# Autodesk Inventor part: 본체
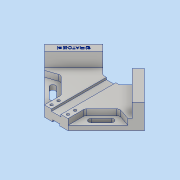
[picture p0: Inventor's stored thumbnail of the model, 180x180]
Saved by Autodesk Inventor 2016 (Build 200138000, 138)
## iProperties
Created: 2019-04
Part Number: 본체
Material: 알루미늄 6061
Document SubType Name: Modeling
Designer: 3sil_cad018
Density: 2.7 g/cm^3
Appearance: 알루미늄 - 평지
Mass: 601.509 g
Surface Area: 426.536 cm^2
Volume: 222.781 cm^3
Author: 3sil_cad018
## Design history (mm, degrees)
sketch "스케치1"
  geometry: L1 (0, -84.853)-(-84.853, 0); L2 (-84.853, 0)-(0, 84.853); L3 (0, 84.853)-(84.853, 0); L4 (84.853, 0)-(0, -84.853); L5 (84.853, 0)-(-84.853, 0); 2 further points
  constraints: 10 end point, 1 coincident, 1 horizontal, 9 other
  dimensions: "d1" = 120 distance of L1.start L1.end
extrude "돌출1" new body sketch "스케치1" distance "d2" = 18; taper "d3" = 0 deg
sketch "스케치2"
  geometry: L1 (0, 18)-(-84.853, 18) reference; L2 (-8, 18)-(-8, 14.5); L3 (-8, 14.5)-(8, 14.5); L4 (8, 14.5)-(8, 18); L5 (84.853, 18)-(0, 18) reference; L6 (0, 0)-(84.853, 0) reference; L7 (8, 0)-(8, 3); L8 (8, 3)-(-8, 3); L9 (-8, 3)-(-8, 0); L10 (8, 0)-(-8, 0); L11 (-84.853, 0)-(0, 0) reference; 1 further point
  constraints: 14 end point, 7 point on line, 4 perpendicular, 1 collinear, 1 midpoint, 1 vertical, 1 vertical alignment
  dimensions: "d4" = 16 distance between parallel lines of L4 L2; "d5" = 3 distance of L7.start L7.end; "d6" = 3.5 distance of L3.end L4.end
extrude "돌출2" cut sketch "스케치2" stored distance "d7" = 1000; taper "d8" = 0 deg
sketch "스케치3"
  geometry: L1 (-84.853, 0)-(-8, -76.853) reference; L2 (-74.246, -10.607)-(10.607, 74.246); L3 (84.853, 0)-(8, 76.853) reference; L4 (8, -76.853)-(84.853, 0) reference; L5 (74.246, -10.607)-(-10.607, 74.246); L6 (-8, 76.853)-(-84.853, 0) reference; L7 (-74.246, -10.607)-(-84.853, 0); L8 (-10.607, 74.246)-(0, 63.64); L9 (10.607, 74.246)-(84.853, 0); L10 (74.246, -10.607)-(84.853, 0); 1 further point
  constraints: 12 end point, 7 point on line, 2 collinear, 1 perpendicular
  dimensions: "d9" = 15 distance between parallel lines of L3 L5; "d10" = 15 distance between parallel lines of L6 L2
extrude "돌출3" join sketch "스케치3" distance "d11" = 24; taper "d12" = 0 deg
sketch "스케치4"
  geometry: L1 (-84.853, 0)-(-8, 76.853) reference; L2 (-35.355, 49.497)-(-14.005, 28.147); L3 (14.005, 28.147)-(35.355, 49.497); L4 (8, 76.853)-(84.853, 0) reference; L5 (-35.355, 49.497)-(0, 84.853); L6 (0, 84.853)-(35.355, 49.497); L7 (-14.005, 28.147)-(14.005, 28.147); L8 (-20, -64.853)-(20, -64.853); L9 (-8, -76.853)-(0, -84.853) reference; L10 (-20, -64.853)-(0, -84.853); L11 (8, -76.853)-(0, -84.853) reference; L12 (0, -84.853)-(20, -64.853); L13 (84.853, 0)-(8, -76.853) reference; 1 further point
  constraints: 16 end point, 2 collinear, 2 horizontal, 2 perpendicular, 2 point on line
  dimensions: "d13" = 50 distance between parallel lines of L2 L6; "d14" = 50 distance between parallel lines of L3 L5; "d15" = 20 distance from line of L9.end L8; "d16" = 93 distance between parallel lines of L8 L7
extrude "돌출4" cut sketch "스케치4" distance "d17" = 100; taper "d18" = 0 deg
node "작업 평면1"
sketch "스케치7"
  geometry: L1 (-35.355, 49.497)-(-84.853, 0) reference; L2 (-49.497, -7.071)-(-20, -36.569); L3 (-74.246, -10.607)-(-20, -64.853) reference; L4 (-20, -64.853)-(-84.853, 0) reference; L5 (-49.497, -7.071)-(-70.711, -14.142); L6 (-70.711, -14.142)-(-42.426, -42.426); L7 (-20, -64.853)-(-8, -64.853) reference; L8 (-20, -64.853)-(-70.711, -14.142); L9 (-20, -64.853)-(-20, -36.569); 1 further point
  constraints: 10 end point, 2 point on line, 1 collinear, 1 perpendicular, 1 vertical
  dimensions: "d31" = 40 distance of L5.end L6.end; "d35" = 63.4349 deg angle of L3 L5; "d38" = 20 distance between parallel lines of L2 L3; "d84" = 20 distance from line of L1 L5.end
extrude "돌출5" cut sketch "스케치7" distance "d39" = 10; taper "d40" = 0 deg
sketch "스케치9"
  geometry: L1 (-20, -64.853)-(-70.711, -14.142) reference; L2 (-35.355, 49.497)-(-84.853, 0) reference; L3 (-49.497, -21.213)-(-32.527, -38.184); L4 (-46.315, -18.031)-(-29.345, -35.002); L5 (-35.709, -41.366)-(-52.679, -24.395); A1 r 4.5 centre (-49.497, -21.213) between (-46.315, -18.031) and (-52.679, -24.395); A2 r 4.5 centre (-32.527, -38.184) between (-35.709, -41.366) and (-29.345, -35.002); 1 further point
  constraints: 6 end point, 4 point on circle, 3 tangent, 2 centre point, 2 coincident
  dimensions: "d46" = 40 distance from line of L2 L3.start; "d48" = 24 distance of L3.start L3.end; "d49" = 9 diameter of A1; "d50" = 9 diameter of A2; "d51" = 10 distance between parallel lines of L1 L3; "d52" = 24 distance of L4.start L4.end
extrude "돌출6" cut sketch "스케치9" distance "d53" = 18; taper "d54" = 0 deg
sketch "스케치10"
  geometry: 1 further point
sketch "스케치11"
  geometry: L1 (-8, -64.853)-(-20, -64.853) reference; L2 (-8, -64.853)-(8, -64.853) reference; 5 further points
  constraints: 4 other
hole "구멍1" sketch "스케치11" at (-14, -46.853), (-14, -58.853), (14, -58.853), (14, -46.853) diameter "d58" = 4.5; stored, may be unused: countersink angle "d62" = 90 deg, drill point angle "d64" = 118 deg; dims "d59" = 6, "d60" = 4, "d61" = 2, "d63" = 8
sketch "스케치12"
  geometry: C1 r 2.25 at (-14, 58.853) reference; C2 r 2.25 at (-14, 46.853) reference; C3 r 2.25 at (14, 46.853) reference; C4 r 2.25 at (14, 58.853) reference; 5 further points
  constraints: 4 coincident
hole "구멍2" sketch "스케치12" at (-14, 58.853), (-14, 46.853), (14, 46.853), (14, 58.853) diameter "d65" = 8; stored, may be unused: countersink angle "d69" = 90 deg, drill point angle "d71" = 0 deg; dims "d66" = 6, "d67" = 4, "d68" = 2, "d70" = 10
fillet "모깎기1" dims "d72" = 5
fillet "모깎기2" dims "d73" = 5
node "작업 평면2"
sketch "스케치13"
  geometry: L1 (-84.853, 0)-(-35.355, 49.497) reference; L2 (-24.749, 38.891)-(-35.355, 49.497) reference; 2 further points
  constraints: 1 other
  dimensions: "d75" = 7.5 distance from line of L1 point (-54.801, 19.445); "d76" = 35 distance from line of point (-54.801, 19.445) L2
feature "엠보싱1" sketch "스케치13" dims "d8" = 0, "d77" = 0.5, "d78" = 0
sketch "스케치15"
  geometry: L1 (0, -11.5)-(16, -11.5) reference; L2 (0, -11.5)-(2, -11.5); L3 (2, -11.5)-(2, -14.5); L4 (2, -14.5)-(0, -14.5); L5 (0, -14.5)-(0, -11.5); L6 (16, -11.5)-(16, -14.5) reference; L7 (16, -11.5)-(14, -11.5); L8 (14, -11.5)-(14, -14.5); L9 (14, -14.5)-(16, -14.5); L10 (16, -14.5)-(16, -11.5); 2 further points
  constraints: 16 end point, 4 parallel, 2 coincident, 2 horizontal, 2 perpendicular, 1 point on line
  dimensions: "d79" = 12 distance between parallel lines of L8 L3; "d80" = 3 distance of L7.end L8.end; "d81" = 2 distance between parallel lines of L8 L6
extrude "돌출7" join sketch "스케치15" distance "d82" = 93; taper "d83" = 0 deg
node "솔리드1"
mirror "대칭1"
mirror "대칭2"
other parameters: "d25" = 0
